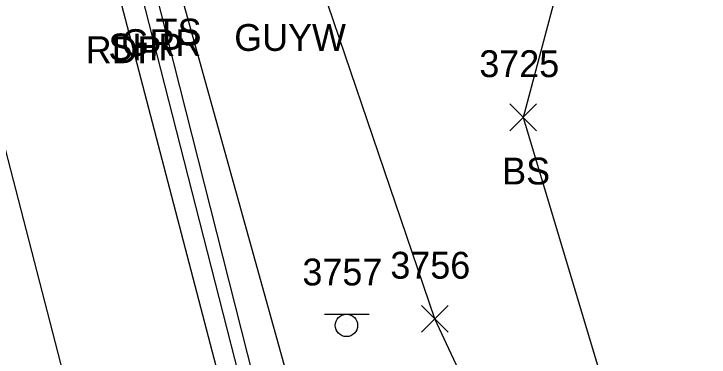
# Model space of a CAD drawing. Extents: x 1601151 to 1602912, y 499508 to 501770.
# Drawn here: x 1601622.4 to 1601674.2, y 500514.8 to 500540.4 of the extents above; entities that cross this region are included whole.
import ezdxf

# ---------------------------------------------------------------- set-up
doc = ezdxf.new("R2010")
doc.units = 0
for name, color, linetype in [('L_A', 7, 'Continuous'), ('L_I', 7, 'Continuous'), ('L_TIC', 7, 'Continuous'), ('LAWA', 7, 'Continuous'), ('LELB', 7, 'Continuous'), ('P_A', 7, 'Continuous'), ('PET', 7, 'Continuous'), ('PRC', 7, 'Continuous'), ('PSP', 7, 'Continuous'), ('R_A', 7, 'Continuous'), ('RGR', 7, 'Continuous'), ('S_I', 7, 'Continuous'), ('SSGN', 7, 'Continuous'), ('U_A', 7, 'Continuous')]:
    doc.layers.add(name, color=color, linetype=linetype)

msp = doc.modelspace()

# ---------------------------------------------------------------- linework, layer by layer
at = {"layer": 'L_TIC'}
for points in [[(1601659.328, 500531.639), (1601661.328, 500533.639)], [(1601661.328, 500531.639), (1601659.328, 500533.639)], [(1601652.753, 500516.616), (1601654.753, 500518.616)], [(1601654.753, 500516.616), (1601652.753, 500518.616)]]:
    msp.add_lwpolyline(points, dxfattribs=at)
at = {"layer": 'LAWA'}
msp.add_lwpolyline([(1601626.124, 500618.106), (1601633.592, 500628.152), (1601648.198, 500633.032), (1601656.043, 500631.466), (1601665.92, 500613.826), (1601678.531, 500593.269), (1601702.446, 500561.858), (1601700.633, 500541.827), (1601700.972, 500520.508), (1601701.434, 500508.423), (1601692.748, 500493.591), (1601673.57, 500488.492), (1601667.988, 500487.133), (1601653.753, 500517.616), (1601642.444, 500550.901)], dxfattribs=at)
at = {"layer": 'LELB'}
for points in [[(1601676.5, 500384.872), (1601670.44, 500406.37), (1601660.93, 500442.547), (1601649.052, 500490.729), (1601634.54, 500542.998), (1601631.677, 500557.447), (1601631.6, 500563.017)], [(1601664.281, 500547.499), (1601660.328, 500532.639), (1601673.57, 500488.492), (1601682.683, 500465.45)]]:
    msp.add_lwpolyline(points, dxfattribs=at)
at = {"layer": 'PET'}
msp.add_lwpolyline([(1601995.672, 499683.239), (1601967.438, 499723.891), (1601951.2, 499747.807), (1601928.383, 499780.817), (1601898.695, 499825.125), (1601866.225, 499874.785), (1601846.19, 499907.837), (1601823.764, 499946.631), (1601805.555, 499981.904), (1601788.872, 500017.294), (1601766.923, 500067.608), (1601755.39, 500098.806), (1601743.924, 500129.717), (1601726.447, 500185.711), (1601711.929, 500234.213), (1601699.419, 500278.305), (1601688.326, 500319.606), (1601682.557, 500342.801), (1601675.526, 500367.537), (1601665.758, 500404.469), (1601656.174, 500441.197), (1601643.947, 500489.359), (1601630.25, 500541.677)], dxfattribs=at)
at = {"layer": 'PRC'}
msp.add_lwpolyline([(1601985.389, 499677.473), (1601958.565, 499716.671), (1601942.322, 499739.604), (1601916.264, 499778.512), (1601888.678, 499819.151), (1601856.543, 499869.05), (1601836.005, 499902.112), (1601813.365, 499942.521), (1601794.976, 499977.026), (1601778.265, 500012.715), (1601755.571, 500062.845), (1601744.487, 500093.78), (1601732.766, 500126.074), (1601715.372, 500182.363), (1601700.572, 500231.277), (1601688.367, 500275.568), (1601676.784, 500317.033), (1601664.233, 500365.849), (1601655.243, 500401.01), (1601645.633, 500438.144), (1601632.995, 500486.745), (1601619.53, 500538.875)], dxfattribs=at)
at = {"layer": 'PSP'}
msp.add_lwpolyline([(1601676.93, 500367.473), (1601676.532, 500368.735), (1601667.013, 500404.766), (1601657.278, 500441.189), (1601645.244, 500489.646), (1601631.9, 500541.89)], dxfattribs=at)
at = {"layer": 'RGR'}
msp.add_lwpolyline([(1601677.319, 500380.62), (1601668.111, 500405.213), (1601658.23, 500441.579), (1601646.231, 500489.648), (1601632.914, 500542.211)], dxfattribs=at)
at = {"layer": 'SSGN'}
for p, q in [((1601645.521, 500517.965), (1601648.854, 500517.965)), ((1601647.167, 500517.132), (1601647.167, 500517.132))]:
    msp.add_line(p, q, dxfattribs=at)
msp.add_circle((1601647.167, 500517.132), 0.833, dxfattribs=at)

# ---------------------------------------------------------------- texts
at = {"layer": 'L_A'}
for s, p in [('TS', (1601632.95, 500537.998)), ('BS', (1601658.769, 500527.639))]:
    msp.add_text(s, height=2, dxfattribs=at).set_placement(p)
at = {"layer": 'L_I'}
for s, p in [('3725', (1601657.068, 500535.639)), ('3756', (1601650.438, 500520.616))]:
    msp.add_text(s, height=2, dxfattribs=at).set_placement(p)
at = {"layer": 'P_A'}
for s, p in [('RDP', (1601627.738, 500536.677)), ('SHP', (1601629.435, 500536.89))]:
    msp.add_text(s, height=2, dxfattribs=at).set_placement(p)
at = {"layer": 'R_A'}
msp.add_text('GRR', height=2, dxfattribs=at).set_placement((1601630.403, 500537.211))
at = {"layer": 'S_I'}
msp.add_text('3757', height=2, dxfattribs=at).set_placement((1601643.888, 500520.112))
at = {"layer": 'U_A'}
msp.add_text('GUYW', height=2, dxfattribs=at).set_placement((1601638.806, 500537.594))

doc.saveas('drawing.dxf')
